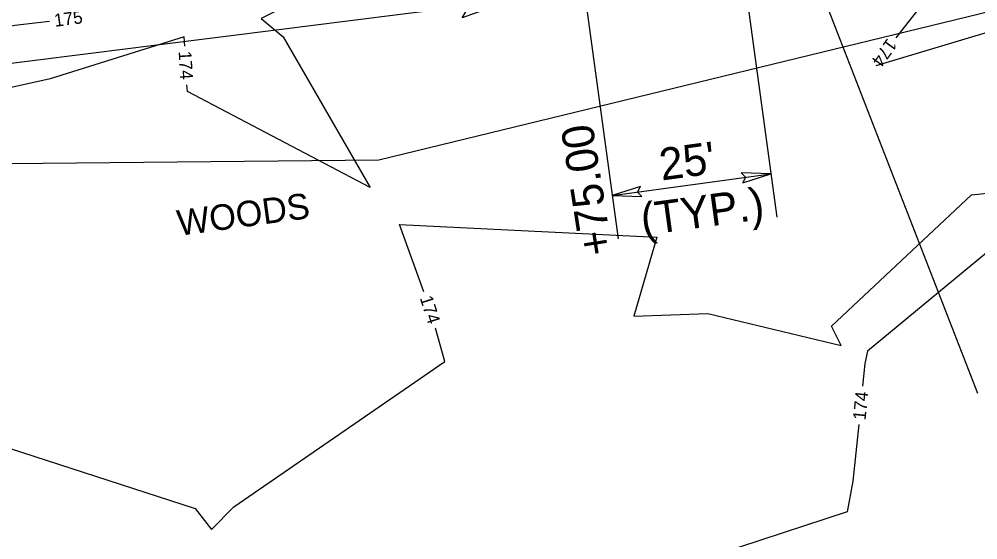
# Model space of a CAD drawing. Extents: x 2086416 to 2115205, y 575507 to 632762.
# Drawn here: x 2112206.5 to 2112356.1, y 581626.3 to 581707.6 of the extents above; entities that cross this region are included whole.
import ezdxf

# ---------------------------------------------------------------- set-up
doc = ezdxf.new("R2010")
doc.units = 0
for name, color, linetype in [('Default', 7, 'Continuous'), ('DTM Contours Major', 7, 'Continuous'), ('DTM Contours Major Text', 7, 'Continuous'), ('DTM Contours Minor', 7, 'Continuous'), ('DTM Contours Minor Text', 7, 'Continuous'), ('Exist Hydrographic FEMA Cross Section', 7, 'Continuous'), ('Exist Right of Way Line', 7, 'Continuous'), ('Exist Vegetation Woods Line', 7, 'Continuous'), ('Exist Vegetation Woods Line Text', 7, 'Continuous'), ('Prop Horizontal Alignment Station Label', 7, 'Continuous')]:
    doc.layers.add(name, color=color, linetype=linetype)

msp = doc.modelspace()

# ---------------------------------------------------------------- linework, layer by layer
at = {"layer": 'Default'}
for p, q in [((2112315.66, 581743.08), (2112324.74, 581676.64)), ((2112290.88, 581739.7), (2112299.95, 581673.26)), ((2112299.03, 581680.04), (2112323.81, 581683.42))]:
    msp.add_line(p, q, dxfattribs=at)
for points in [[(2112319.4, 581682.03), (2112323.81, 581683.42), (2112319.16, 581683.6), (2112319.84, 581682.88)], [(2112303.43, 581681.43), (2112299.03, 581680.04), (2112303.67, 581679.86), (2112302.99, 581680.58)]]:
    msp.add_lwpolyline(points, close=True, dxfattribs=at)
at = {"layer": 'DTM Contours Major'}
msp.add_lwpolyline([(2112115.35, 581698.13), (2112120.53, 581693.14), (2112134.17, 581691.59), (2112156.79, 581693.38), (2112161.11, 581695.13), (2112179.46, 581698.78), (2112193.13, 581703.79), (2112205.82, 581706.66), (2112209.41, 581707.04), (2112211.23, 581707.28)], dxfattribs=at)
at = {"layer": 'DTM Contours Minor'}
for points in [[(2112343.34, 581704.65), (2112350.12, 581713.38), (2112332.97, 581725.6), (2112308.89, 581715.82), (2112296.37, 581715.24), (2112275.63, 581707.81), (2112279.07, 581713.44), (2112269.95, 581714.02), (2112259.58, 581711.35), (2112249.1, 581710.06), (2112244.24, 581707.7), (2112247.67, 581704.8), (2112261.26, 581681.31), (2112232.74, 581696.26), (2112232.68, 581697.35)], [(2112361.21, 581706.57), (2112340.17, 581700.27)], [(2112232.33, 581703.34), (2112232.24, 581704.8), (2112211.35, 581698.28), (2112205.02, 581696.84), (2112184.7, 581689.39), (2112179.33, 581672.48), (2112183.71, 581663.85), (2112184.18, 581659.93), (2112183.36, 581652.63), (2112202.94, 581641.22), (2112233.96, 581631.14), (2112236.48, 581627.86), (2112240, 581631.41), (2112272.92, 581654.12), (2112271.45, 581659.3)], [(2112269.63, 581665.02), (2112265.85, 581675.53), (2112305.98, 581673.56), (2112302.41, 581661.19), (2112313.97, 581661.63), (2112334.75, 581656.62), (2112333.25, 581659.62), (2112355.11, 581680.12), (2112364.82, 581681.18), (2112374.16, 581680.98), (2112368.35, 581676.12), (2112364.61, 581677.02), (2112338.85, 581655.74), (2112338.48, 581653.78), (2112338.11, 581650.24)], [(2112337.5, 581644.27), (2112336.58, 581635.42), (2112335.7, 581630.66), (2112312.26, 581622.94), (2112297.16, 581620.89), (2112294.63, 581606.21), (2112290.94, 581585.17), (2112290.56, 581581.19), (2112292.27, 581575.91), (2112290.35, 581556.21), (2112291.44, 581551.51), (2112286.69, 581531.27), (2112286.24, 581528.95), (2112276.21, 581516.73)]]:
    msp.add_lwpolyline(points, dxfattribs=at)
at = {"layer": 'Exist Hydrographic FEMA Cross Section'}
msp.add_lwpolyline([(2112356.49, 581719.74), (2112346.58, 581718.49), (2112341.62, 581717.86), (2112336.66, 581717.24), (2112326.74, 581715.99), (2112316.82, 581714.73), (2112306.91, 581713.48), (2112296.99, 581712.23), (2112287.07, 581710.98), (2112277.16, 581709.73), (2112267.24, 581708.48), (2112257.32, 581707.22), (2112247.41, 581705.97), (2112237.49, 581704.72), (2112227.57, 581703.47), (2112217.66, 581702.22), (2112207.74, 581700.97), (2112201.88, 581700.22), (2111922.67, 581647.71)], dxfattribs=at)
at = {"layer": 'Exist Right of Way Line'}
msp.add_arc((2100483.79, 667614.96), 86697.25, 277.6423877, 277.7710056, dxfattribs=at)
at = {"layer": 'Exist Vegetation Woods Line'}
msp.add_lwpolyline([(2112111.96, 581666.92), (2112111.49, 581680.94), (2112152.5, 581684.53), (2112262.63, 581685.59), (2112360.38, 581709.42), (2112461.66, 581723.72), (2112531.13, 581752.37)], dxfattribs=at)
at = {"layer": 'Prop Horizontal Alignment Station Label'}
msp.add_line((2112356.11, 581649.1), (2112313.51, 581758.79), dxfattribs=at)

# ---------------------------------------------------------------- texts
at = {"layer": 'Default'}
for s, rotation, p in [('+75.00', 98.8197, (2112299.1, 581671.05)), ("25'", 7.771, (2112306.75, 581682.37)), ('(TYP.)', 7.771, (2112303.84, 581673.78))]:
    msp.add_text(s, height=5, rotation=rotation, dxfattribs=at).set_placement(p)
at = {"layer": 'DTM Contours Major Text'}
msp.add_text('175', height=2, rotation=7.5775, dxfattribs=at).set_placement((2112212.08, 581706.38))
at = {"layer": 'DTM Contours Minor Text'}
for rotation, p in [(234.1752, (2112342.02, 581704.72)), (273.3548, (2112231.37, 581702.55)), (287.7292, (2112268.99, 581664.05)), (84.0922, (2112338.56, 581644.89))]:
    msp.add_text('174', height=2, rotation=rotation, dxfattribs=at).set_placement(p)
at = {"layer": 'Exist Vegetation Woods Line Text'}
msp.add_text('WOODS', height=4, rotation=7.771, dxfattribs=at).set_placement((2112231.43, 581673.73))

doc.saveas('drawing.dxf')
